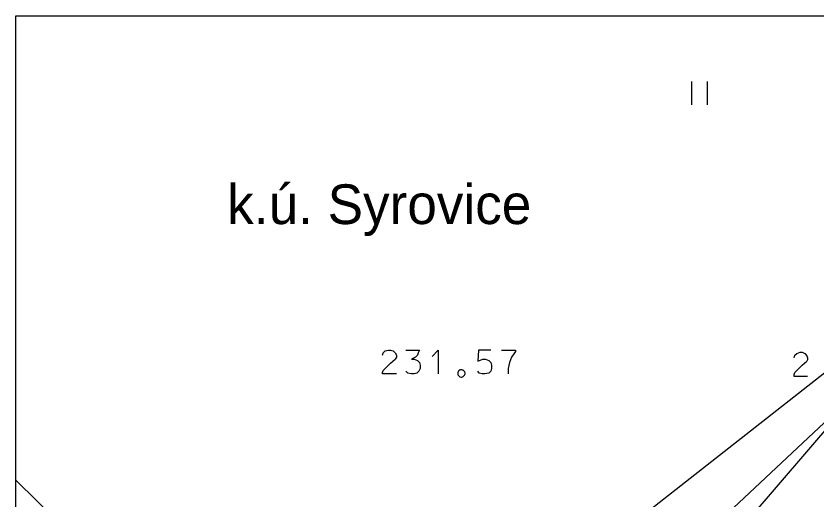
# Model space of a CAD drawing. Extents: x -603337.1 to -603289.6, y -1172912.5 to -1172843.3.
# Drawn here: x -603337.13 to -603311.96, y -1172858.46 to -1172843.25 of the extents above; entities that cross this region are included whole.
import ezdxf

# ---------------------------------------------------------------- set-up
doc = ezdxf.new("R2010")
doc.units = 0
for name, color, linetype in [('GEODET', 7, 'Continuous'), ('Popis_k_ú_250', 7, 'Continuous'), ('Rámeček A4 1_250', 7, 'Continuous'), ('sdělovací vedení NET4GAS', 7, 'Continuous'), ('Vnitřní kresba', 7, 'Continuous')]:
    doc.layers.add(name, color=color, linetype=linetype)

msp = doc.modelspace()

# ---------------------------------------------------------------- linework, layer by layer
at = {"layer": 'GEODET'}
for p, q in [((-603315.865, -1172846.051), (-603315.865, -1172845.31)), ((-603315.378, -1172846.051), (-603315.378, -1172845.31)), ((-603324.861, -1172853.777), (-603324.438, -1172853.777)), ((-603323.845, -1172853.777), (-603324.036, -1172853.967)), ((-603323.845, -1172853.777), (-603323.845, -1172854.517)), ((-603322.575, -1172853.777), (-603322.596, -1172854.115)), ((-603322.194, -1172853.777), (-603322.575, -1172853.777)), ((-603321.856, -1172853.777), (-603321.411, -1172853.777)), ((-603321.411, -1172853.777), (-603321.411, -1172853.819)), ((-603325.581, -1172854.412), (-603325.348, -1172854.179)), ((-603325.348, -1172854.179), (-603325.2, -1172854.052)), ((-603312.627, -1172854.475), (-603312.394, -1172854.242)), ((-603312.394, -1172854.242), (-603312.246, -1172854.115)), ((-603325.602, -1172854.475), (-603325.581, -1172854.412)), ((-603325.602, -1172854.517), (-603325.602, -1172854.475)), ((-603325.157, -1172854.517), (-603325.602, -1172854.517)), ((-603312.648, -1172854.539), (-603312.627, -1172854.475)), ((-603312.648, -1172854.602), (-603312.648, -1172854.539)), ((-603319.506, -1172863.365), (-603310.15, -1172854.602)), ((-603312.225, -1172854.602), (-603312.648, -1172854.602))]:
    msp.add_line(p, q, dxfattribs=at)
for points in [[(-603325.602, -1172853.925), (-603325.581, -1172853.861), (-603325.517, -1172853.798), (-603325.412, -1172853.777), (-603325.348, -1172853.777), (-603325.263, -1172853.798)], [(-603324.438, -1172853.777), (-603324.48, -1172853.861), (-603324.501, -1172853.925), (-603324.565, -1172853.988), (-603324.692, -1172854.052)], [(-603325.263, -1172853.798), (-603325.2, -1172853.861), (-603325.157, -1172853.925), (-603325.157, -1172853.988), (-603325.2, -1172854.052)], [(-603321.411, -1172853.819), (-603321.538, -1172853.988), (-603321.601, -1172854.157), (-603321.644, -1172854.348), (-603321.644, -1172854.517)], [(-603312.648, -1172854.009), (-603312.627, -1172853.925), (-603312.563, -1172853.882), (-603312.458, -1172853.84), (-603312.394, -1172853.84), (-603312.309, -1172853.882)], [(-603312.309, -1172853.882), (-603312.246, -1172853.946), (-603312.225, -1172854.009), (-603312.225, -1172854.073), (-603312.246, -1172854.115)], [(-603337.132, -1172872.534), (-603321.813, -1172862.434), (-603311.145, -1172854.052)], [(-603324.692, -1172854.052), (-603324.607, -1172854.052), (-603324.501, -1172854.094), (-603324.438, -1172854.157), (-603324.417, -1172854.242), (-603324.417, -1172854.348), (-603324.459, -1172854.433), (-603324.523, -1172854.496), (-603324.607, -1172854.517), (-603324.692, -1172854.517), (-603324.798, -1172854.496), (-603324.861, -1172854.433)], [(-603322.596, -1172854.115), (-603322.448, -1172854.052), (-603322.363, -1172854.052), (-603322.258, -1172854.094), (-603322.194, -1172854.157), (-603322.173, -1172854.242), (-603322.173, -1172854.306)], [(-603322.173, -1172854.306), (-603322.173, -1172854.348), (-603322.194, -1172854.433), (-603322.258, -1172854.496), (-603322.385, -1172854.517), (-603322.469, -1172854.517), (-603322.554, -1172854.496), (-603322.596, -1172854.433)]]:
    msp.add_lwpolyline(points, dxfattribs=at)
for centre, radius, start, end in [((-603323.111, -1172854.495), 0.12, 159.5232, 180.5607), ((-603323.09, -1172854.497), 0.142, 179.4975, 217.3724), ((-603323.134, -1172854.487), 0.0957, 135.2549, 159.2174), ((-603323.135, -1172854.487), 0.0957, 110.7826, 134.7451), ((-603323.127, -1172854.511), 0.12, 89.4393, 110.4768), ((-603323.124, -1172854.532), 0.142, 52.6276, 90.5025), ((-603323.097, -1172854.498), 0.0983, 1.2874, 53.4124), ((-603323.139, -1172854.481), 0.144, 314.736, 334.7191), ((-603323.109, -1172854.495), 0.111, 334.319, 359.3359), ((-603323.123, -1172854.525), 0.0983, 216.5876, 268.7126), ((-603323.127, -1172854.513), 0.111, 270.6641, 295.681), ((-603323.14, -1172854.482), 0.144, 295.2809, 315.264)]:
    msp.add_arc(centre, radius, start, end, dxfattribs=at)
at = {"layer": 'Rámeček A4 1_250'}
msp.add_lwpolyline([(-603337.132, -1172843.252), (-603289.632, -1172843.252), (-603289.632, -1172912.502), (-603337.132, -1172912.502)], close=True, dxfattribs=at)
at = {"layer": 'sdělovací vedení NET4GAS'}
msp.add_lwpolyline([(-603337.132, -1172857.87), (-603333.743, -1172861.208), (-603325.907, -1172866.9), (-603324.273, -1172868.552), (-603321.234, -1172870.846), (-603315.762, -1172874.254), (-603312.852, -1172876.305), (-603308.035, -1172879.34), (-603301.936, -1172884.901), (-603293.588, -1172890.72), (-603291.824, -1172893.098)], dxfattribs=at)
at = {"layer": 'Vnitřní kresba'}
msp.add_line((-603307.99, -1172851.99), (-603314.73, -1172859.85), dxfattribs=at)

# ---------------------------------------------------------------- texts
at = {"layer": 'Popis_k_ú_250'}
msp.add_text('k.ú. Syrovice', height=1.25, dxfattribs=at).set_placement((-603330.485, -1172849.803))

doc.saveas('drawing.dxf')
